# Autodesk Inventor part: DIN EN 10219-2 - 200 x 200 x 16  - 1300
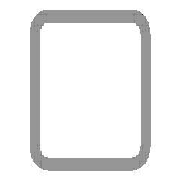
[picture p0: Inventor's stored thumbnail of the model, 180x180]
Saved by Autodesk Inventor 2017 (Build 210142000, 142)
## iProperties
Created: 2017-11
Part Number: DIN EN 10219-2 - 200 x 200 x 16  - 1300
Material: Steel, Mild
Description: Cold formed welded structural hollow sections of non-alloy and fine grain structural steel
Document SubType Name: Modeling
Standard: DIN
Designer: iusti
Standard Revision: 2006-07
Standards Organization: DIN
Language: en-US
Size Designation: 200 x 200 x 16
Categories: <MemberInstance><Categories><Category DisplayName="Structural Shapes" InternalName="089c4875-fa83-4c05-b084-43b9cc11f5ed" Mnemonic="GRDR"><CategoryParameter Dis
Stock Number: 200 x 200 x 16
Mass: 108961 g
Surface Area: 17564.1 cm^2
Volume: 13880.4 cm^3
Density: 7.85 g/cm^3
Appearance: Semi-Polished
_CCFamilyMember: 103
_CCFamilyDisplayName: DIN EN 10219-2 (Square Hollow Section - Cold Formed) - Cold formed welded structural hollow sections of non-alloy and fine grain structural steel
_FrameMemberDoc: Frame Member File
_Version: 15.0.0
_GetPNFromCC: 1
G_L: 1300.000 mm
G_W: 200.000 mm
G_H: 200.000 mm
+6A2F0504-0522-4D64-B7B8-70050364F92E+CUTDETAIL1: Cut
+3EEB6A9D-7D4A-469C-884C-F4929F57B2CA+CUTDETAIL2: Cut
IsCustomPart: 1
Author: iusti
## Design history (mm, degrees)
node "Start plane"
node "End plane"
sketch "Sketch"
  geometry: L1 (-100, -52)-(-100, 52); L2 (-52, 100)-(52, 100); L3 (100, 52)-(100, -52); L4 (52, -100)-(-52, -100); L5 (-52, 84)-(52, 84); L6 (84, 52)-(84, -52); L7 (52, -84)-(-52, -84); L8 (-84, -52)-(-84, 52); L9 (0, 153.918)-(0, -153.918) reference; L10 (-153.918, 0)-(153.918, 0) reference; A1 r 48 centre (-52, -52) between (-100, -52) and (-52, -100); A2 r 48 centre (-52, 52) between (-52, 100) and (-100, 52); A3 r 48 centre (52, 52) between (100, 52) and (52, 100); A4 r 48 centre (52, -52) between (52, -100) and (100, -52); A5 r 32 centre (-52, 52) between (-52, 84) and (-84, 52); A6 r 32 centre (52, 52) between (84, 52) and (52, 84); A7 r 32 centre (52, -52) between (52, -84) and (84, -52); A8 r 32 centre (-52, -52) between (-84, -52) and (-52, -84)
  constraints: 16 end point, 16 point on circle, 8 centre point, 8 tangent, 4 parallel, 3 equal radius, 2 perpendicular, 7 other
  dimensions: "d7" = 48 radius of A1 (= G_IR); "d10" = 200 distance between parallel lines of L2 L4 (= G_H); "d11" = 200 distance between parallel lines of L1 L3 (= G_W); "d12" = 16 distance between parallel lines of L3 L6 (= G_T); "d15" = 100 distance between parallel lines of L2 L10 (= 0.5 x d10); "d16" = 100 distance between parallel lines of L9 L3 (= 0.5 x d11)
extrude "Body" new body sketch "Sketch" stored distance "d3" = 1300 (= G_L); taper "d4" = 0 deg
node "Driven Length"
  sketch "Sketch3"
    geometry: L1 (0, 0)-(10, 0) reference
    constraints: 2 end point, 1 horizontal
  workplane "Work Plane3"
  sketch "Sketch4"
    geometry: L1 (-2, 100)-(12, 100) reference; L2 (-2, 1400)-(12, 1400) reference
    dimensions: "d18" = 1300 distance between parallel lines of L1 L2 (derived)
workplane "Work Plane4"
split "Split1"
workplane "Work Plane5"
split "Split2"
body "Solid1"
other parameters: "G_W" = 200 [user parameter; used in 1 equation term], "G_H" = 200 [user parameter; used in 1 equation term], "G_T" = 16 [user parameter; used in 1 equation term], "G_IR" = 48 [user parameter; used in 1 equation term], "G_L" = 1300 (= d18) [user parameter; used in 1 equation term], "d17" = 90 deg
